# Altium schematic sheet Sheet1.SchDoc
size A4
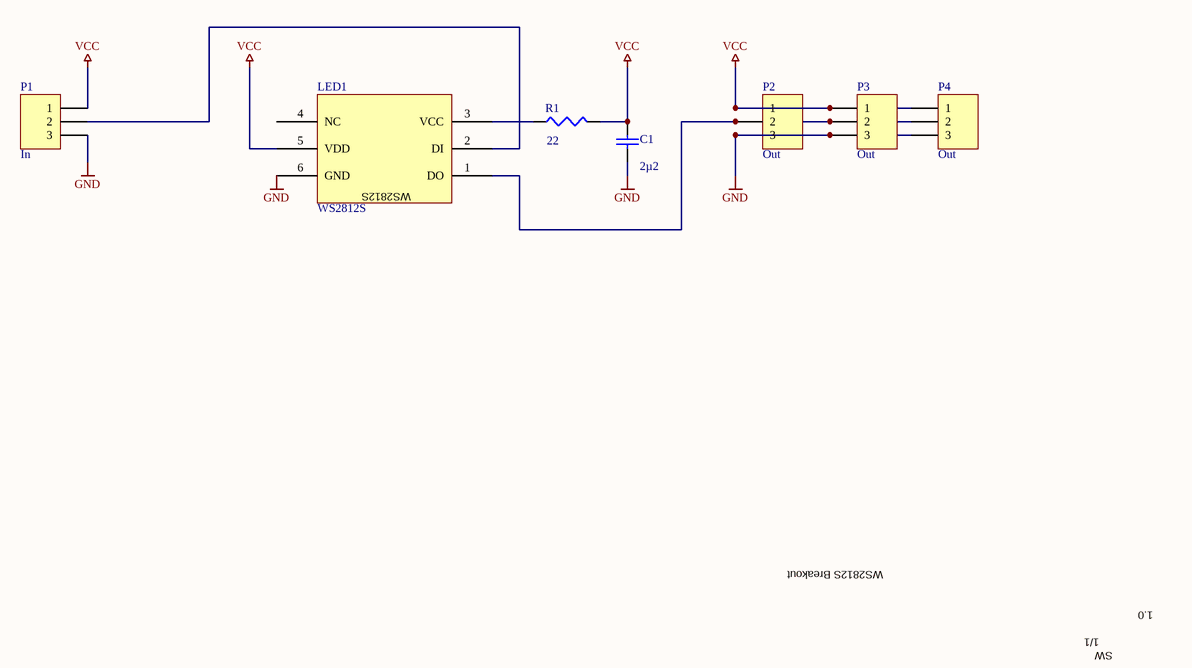
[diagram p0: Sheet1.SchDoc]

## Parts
C1  2µ2  [0603]
LED1  WS2812S  [LED_5050]
P1  In  [HDR1X3]
P2  Out  [HDR1X3]
P3  Out  [HDR1X3]
P4  Out  [HDR1X3]
R1  22  [J1-0603]

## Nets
GND: C1.1 LED1.6(GND) P1.3 P2.3 P3.3 P4.3
VCC: C1.2 LED1.5(VDD) P1.1 P2.1 P3.1 P4.1 R1.2
NetLED1_1: LED1.1(DO) P2.2 P3.2 P4.2
NetLED1_2: LED1.2(DI) P1.2
NetLED1_3: LED1.3(VCC) R1.1

Not connected (* = marked no-connect by the designer): LED1 4(NC)

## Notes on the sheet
- WS2812S Breakout
- 1/1
- SW
- 1.0

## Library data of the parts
C1 = C0603: Ceramic Chip Capacitor - Standard; Note: Footprint corresponds to dimensions for bulk cassette packaging. This case size has tightened tolerances.
P1-P4 = Header 3: Header, 3-Pin
R1 = Res3: Resistor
